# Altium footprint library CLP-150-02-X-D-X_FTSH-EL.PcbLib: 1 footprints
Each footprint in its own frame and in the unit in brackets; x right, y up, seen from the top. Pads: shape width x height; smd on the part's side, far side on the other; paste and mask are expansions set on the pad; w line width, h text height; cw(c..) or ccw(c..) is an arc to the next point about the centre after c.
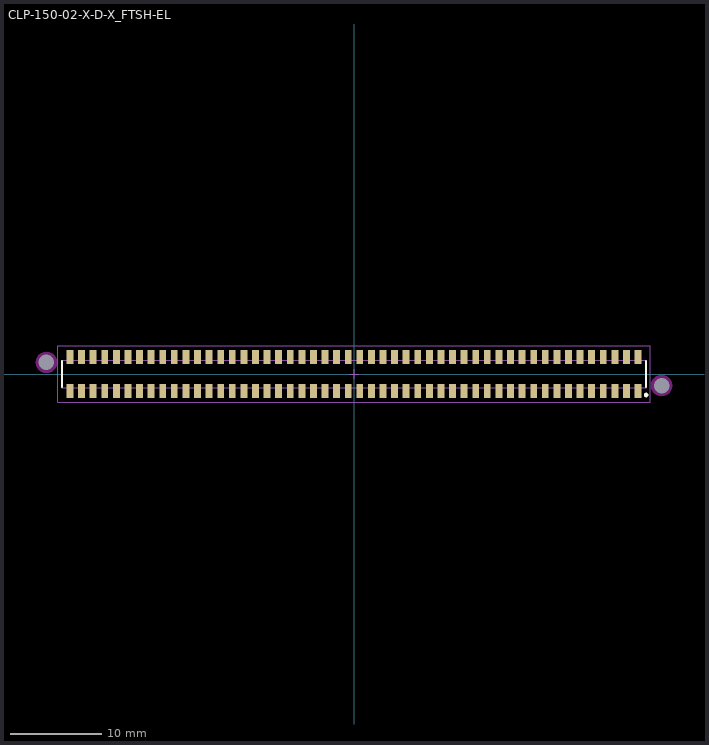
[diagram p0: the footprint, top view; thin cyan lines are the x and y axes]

## CLP-150-02-X-D-X_FTSH-EL [mm] "1.27mm pitch, 100 pin, socket strip; low profile, vertical"
height 2.26
pads (102):
  rect 0.75x1.5 smd mask+0: 1(31.115,-1.87) 2(31.115,1.87) 3(29.845,-1.87) 4(29.845,1.87) 5(28.575,-1.87) 6(28.575,1.87) 7(27.305,-1.87) 8(27.305,1.87) 9(26.035,-1.87) 10(26.035,1.87) 11(24.765,-1.87) 12(24.765,1.87) 13(23.495,-1.87) 14(23.495,1.87) 15(22.225,-1.87) 16(22.225,1.87) 17(20.955,-1.87) 18(20.955,1.87) 19(19.685,-1.87) 20(19.685,1.87) 21(18.415,-1.87) 22(18.415,1.87) 23(17.145,-1.87) 24(17.145,1.87) 25(15.875,-1.87) 26(15.875,1.87) 27(14.605,-1.87) 28(14.605,1.87) 29(13.335,-1.87) 30(13.335,1.87) 31(12.065,-1.87) 32(12.065,1.87) 33(10.795,-1.87) 34(10.795,1.87) 35(9.525,-1.87) 36(9.525,1.87) 37(8.255,-1.87) 38(8.255,1.87) 39(6.985,-1.87) 40(6.985,1.87) 41(5.715,-1.87) 42(5.715,1.87) 43(4.445,-1.87) 44(4.445,1.87) 45(3.175,-1.87) 46(3.175,1.87) 47(1.905,-1.87) 48(1.905,1.87) 49(0.635,-1.87) 50(0.635,1.87) 51(-0.635,-1.87) 52(-0.635,1.87) 53(-1.905,-1.87) 54(-1.905,1.87) 55(-3.175,-1.87) 56(-3.175,1.87) 57(-4.445,-1.87) 58(-4.445,1.87) 59(-5.715,-1.87) 60(-5.715,1.87) 61(-6.985,-1.87) 62(-6.985,1.87) 63(-8.255,-1.87) 64(-8.255,1.87) 65(-9.525,-1.87) 66(-9.525,1.87) 67(-10.795,-1.87) 68(-10.795,1.87) 69(-12.065,-1.87) 70(-12.065,1.87) 71(-13.335,-1.87) 72(-13.335,1.87) 73(-14.605,-1.87) 74(-14.605,1.87) 75(-15.875,-1.87) 76(-15.875,1.87) 77(-17.145,-1.87) 78(-17.145,1.87) 79(-18.415,-1.87) 80(-18.415,1.87) 81(-19.685,-1.87) 82(-19.685,1.87) 83(-20.955,-1.87) 84(-20.955,1.87) 85(-22.225,-1.87) 86(-22.225,1.87) 87(-23.495,-1.87) 88(-23.495,1.87) 89(-24.765,-1.87) 90(-24.765,1.87) 91(-26.035,-1.87) 92(-26.035,1.87) 93(-27.305,-1.87) 94(-27.305,1.87) 95(-28.575,-1.87) 96(-28.575,1.87) 97(-29.845,-1.87) 98(-29.845,1.87) 99(-31.115,-1.87) 100(-31.115,1.87)
  round 1 hole 1.7 unplated mask+0: 101(-33.695,1.27) 102(33.695,-1.27)
Top Overlay:
  circle w0.25: c32,-2.3 r0.125
  lines w0.2: -32,-1.45 -32,1.45 ; 32,-1.45 32,1.45
Keep-Out Layer:
  pour cut-out: -32.535,1.27 -32.575,1.57 -32.69,1.85 -32.875,2.09 -33.115,2.275 -33.395,2.39 -33.695,2.43 -33.995,2.39 -34.275,2.275 -34.515,2.09 -34.7,1.85 -34.815,1.57 -34.855,1.27 -34.815,0.97 -34.7,0.69 -34.515,0.45 -34.275,0.265 -33.995,0.15 -33.695,0.11 -33.395,0.15 -33.115,0.265 -32.875,0.45 -32.69,0.69 -32.575,0.97
  pour cut-out: 34.855,-1.27 34.815,-0.97 34.7,-0.69 34.515,-0.45 34.275,-0.265 33.995,-0.15 33.695,-0.11 33.395,-0.15 33.115,-0.265 32.875,-0.45 32.69,-0.69 32.575,-0.97 32.535,-1.27 32.575,-1.57 32.69,-1.85 32.875,-2.09 33.115,-2.275 33.395,-2.39 33.695,-2.43 33.995,-2.39 34.275,-2.275 34.515,-2.09 34.7,-1.85 34.815,-1.57
Mechanical 12:
  lines w0.001: -32,-1.5 32,-1.5 32,1.5 -32,1.5 -32,-1.5
Mechanical 13:
  lines w0.1: -32,-1.5 32,-1.5 32,1.5 -32,1.5 -32,-1.5
  text ".Designator" at 0.254,0.254 h1.52
Mechanical 15:
  lines w0.05: -0.5,0 0.5,0 ; 0,-0.5 0,0.5 ; -32.461,-3.099 32.461,-3.099 32.461,3.099 -32.461,3.099 -32.461,-3.099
